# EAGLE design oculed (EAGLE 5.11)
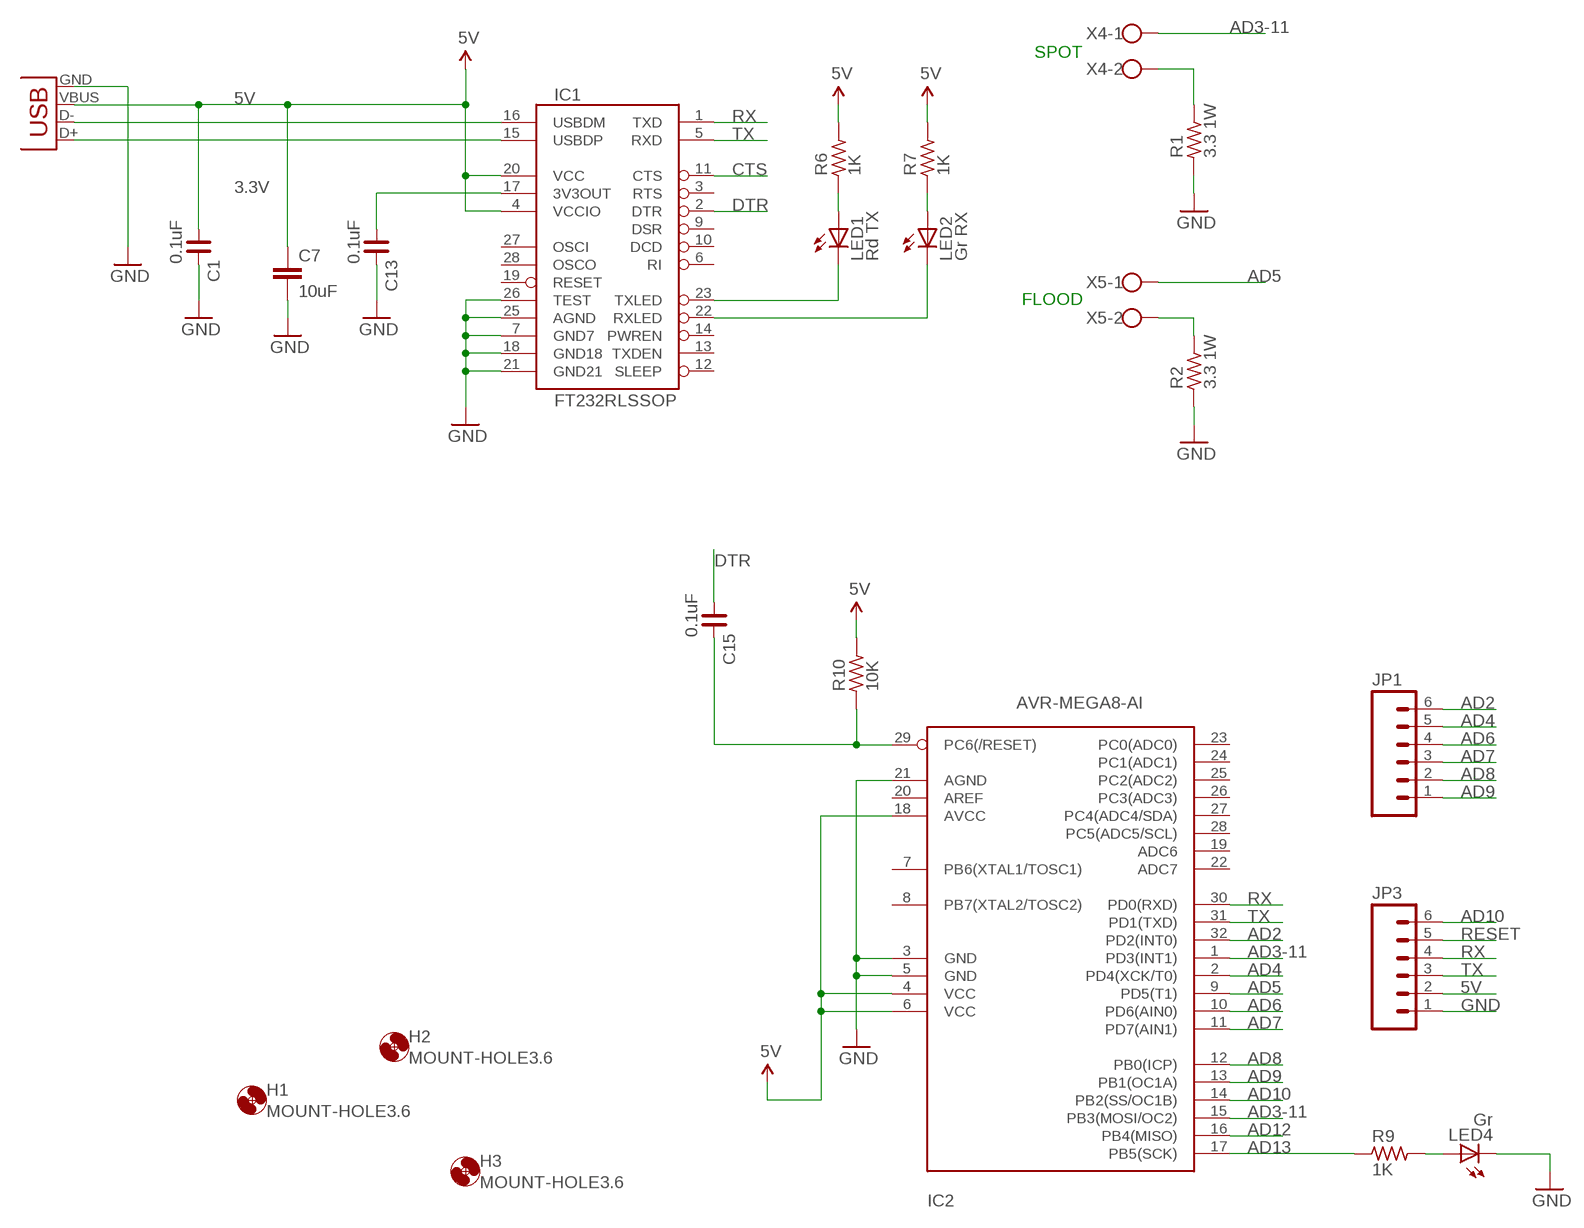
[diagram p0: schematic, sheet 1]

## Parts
C1  0.1uF  C_0805  [C0805]
C7  10uF  C-EUC3216  [C3216]
C13  0.1uF  C_0805  [C0805]
C15  0.1uF  C_0805  [C0805]
H1  MOUNT-HOLE3.6  [3,6]
H2  MOUNT-HOLE3.6  [3,6]
H3  MOUNT-HOLE3.6  [3,6]
IC1  FT232RLSSOP  [SSOP28DB]
IC2  AVR-MEGA8-AI  [TQFP32-08]
JP1  M06LONGPADS  [1X06_LONGPADS]
JP3  M06LONGPADS  [1X06_LONGPADS]
LED1  Rd TX  LEDCHIPLED_0805  [CHIPLED_0805]
LED2  Gr RX  LEDCHIPLED_0805  [CHIPLED_0805]
LED4  Gr  LEDCHIPLED_0805  [CHIPLED_0805]
R1  3.3 1W  R_2512  [R2512]
R2  3.3 1W  R_2512  [R2512]
R6  1K  R_0805  [R0805]
R7  1K  R_0805  [R0805]
R9  1K  R_0805  [R0805]
R10  10K  R_0805  [R0805]
X1  USBSMD  [USB-MINIB]
X4  W237-102  [W237-102]
X5  W237-102  [W237-102]

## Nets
3.3V: C13.1 IC1.17(3V3OUT)
5V [power]: C1.1 C7.1 IC1.4(VCCIO) IC1.20(VCC) IC2.4(VCC) IC2.6(VCC) IC2.18(AVCC) JP3.2 R6.2 R7.2 R10.2 X1.VBUS
AD2: IC2.32(PD2(INT0)) JP1.6
AD3-11: IC2.1(PD3(INT1)) IC2.15(PB3(MOSI/OC2)) X4.1
AD4: IC2.2(PD4(XCK/T0)) JP1.5
AD5: IC2.9(PD5(T1)) X5.1
AD6: IC2.10(PD6(AIN0)) JP1.4
AD7: IC2.11(PD7(AIN1)) JP1.3
AD8: IC2.12(PB0(ICP)) JP1.2
AD9: IC2.13(PB1(OC1A)) JP1.1
AD10: IC2.14(PB2(SS/OC1B)) JP3.6
AD12: IC2.16(PB4(MISO))
AD13: IC2.17(PB5(SCK)) R9.1
CTS: IC1.11(CTS)
DTR: C15.1 IC1.2(DTR)
GND [power]: C1.2 C7.2 C13.2 IC1.7(GND7) IC1.18(GND18) IC1.21(GND21) IC1.25(AGND) IC1.26(TEST) IC2.3(GND) IC2.5(GND) IC2.21(AGND) JP3.1 LED4.C R1.1 R2.1 X1.GND
N$1: IC1.16(USBDM) X1.D-
N$2: LED1.A R6.1
N$3: LED2.A R7.1
N$4: IC1.15(USBDP) X1.D+
N$5: IC1.23(TXLED) LED1.C
N$6: IC1.22(RXLED) LED2.C
N$7 [power]: R1.2 X4.2
N$8 [power]: R2.2 X5.2
N$10: LED4.A R9.2
RESET: C15.2 IC2.29(PC6(/RESET)) JP3.5 R10.1
RX: IC1.1(TXD) IC2.30(PD0(RXD)) JP3.4
TX: IC1.5(RXD) IC2.31(PD1(TXD)) JP3.3
Unconnected: IC1.3(RTS) IC1.6(RI) IC1.9(DSR) IC1.10(DCD) IC1.12(SLEEP) IC1.13(TXDEN) IC1.14(PWREN) IC1.19(RESET) IC1.27(OSCI) IC1.28(OSCO) IC2.7(PB6(XTAL1/TOSC1)) IC2.8(PB7(XTAL2/TOSC2)) IC2.19(ADC6) IC2.20(AREF) IC2.22(ADC7) IC2.23(PC0(ADC0)) IC2.24(PC1(ADC1)) IC2.25(PC2(ADC2)) IC2.26(PC3(ADC3)) IC2.27(PC4(ADC4/SDA)) IC2.28(PC5(ADC5/SCL))

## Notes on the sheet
- SPOT
- FLOOD

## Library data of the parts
C1 C13 C15 = rc-master-smd:C_: NON-POLARIZED CAP
C7 = rcl:C-EU: CAPACITOR, European symbol
H1-H3 = holes:MOUNT-HOLE: MOUNTING HOLE with drill center marker
IC1 = SparkFun:FT232RL: USB UART FT232RL 4th Generation USB UART (USB <-> Serial) Controller. Spark Fun Electronics SKU : COM-00650
IC2 = SparkFun:AVR-MEGA8: MICROCONTROLLER 8 Kbytes FLASH 1 kbytes SRAM 512 bytes EEPROM USART 6-channel 10 bit ADC 2-channel 8 bit ADC
JP1 JP3 = SparkFun:M06: Header 6 Standard 6-pin 0.1" header. Use with straight break away headers (SKU : PRT-00116), right angle break away headers (PRT-00553), swiss pins (PRT-00743), machine pins (PRT-00117), and female headers (PRT-00115). Molex polarized connector foot print use with SKU : PRT-08094 with associated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
LED1 LED2 LED4 = led:LED: LED
R1 R2 R6 R7 R9 R10 = rc-master-smd:R_: RESISTOR
X1 = SparkFun:USB: USB Connectors USB-B-PTH is fully proven SKU : PRT-00139 USB-miniB is fully proven SKU : PRT-00587 USB-A-PCB is untested. USB-A-H is throughly reviewed, but untested. Spark Fun Electronics SKU : PRT-00437 USB-B-SMT is throughly reviewed, but untested. Needs silkscreen touching up. USB-A-S has not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
X4 X5 = con-wago-500:W237-102: WAGO SCREW CLAMP

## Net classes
0 default: width 0.254 mm, drill 0.203 mm, clearance 0.203 mm
1 power: width 0.406 mm, drill 0.254 mm, clearance 0.305 mm

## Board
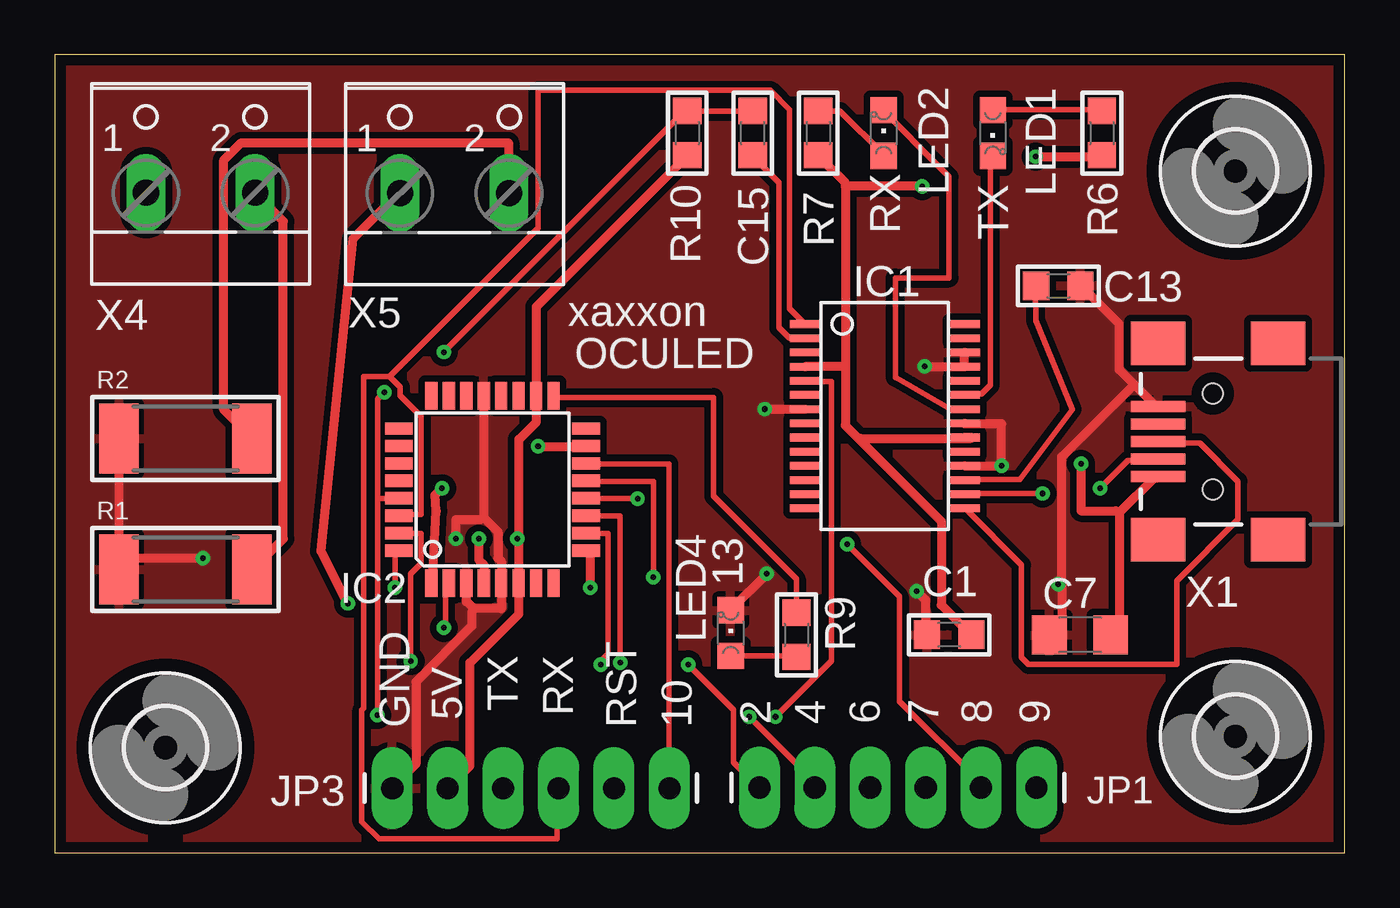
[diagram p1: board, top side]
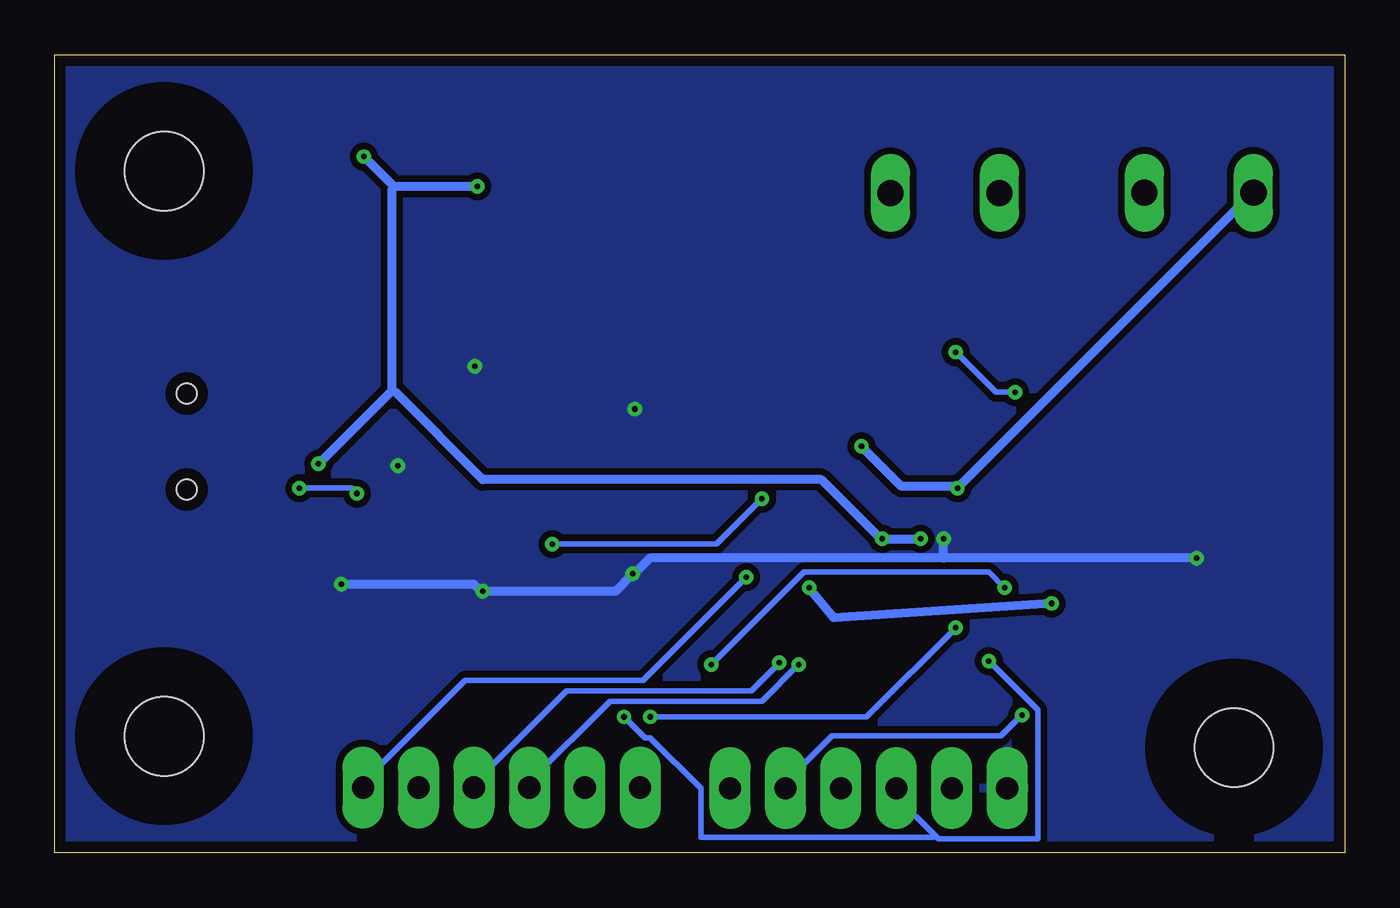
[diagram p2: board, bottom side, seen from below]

Size 59.14 x 36.6 mm. Coordinates in mm from the lower left corner, seen from the top.
Outline: 0,0 59.14,0 59.14,36.6 0,36.6 0,0
Copper layers (1*16): Top 0.035mm / dielectric 1.5mm / Bottom 0.035mm
Design rules "default *": minimum track width 8mil, minimum drill 10mil, track to track 8mil, track to pad 8mil, pad to pad 8mil, via to via 8mil, smd to smd 8mil, copper to edge 20mil, drill to drill 8mil, minimum pad ring 10mil, minimum via ring 8mil, stop-mask expansion 4mil, vias tented up to drill 0mil, thermal gap 10mil

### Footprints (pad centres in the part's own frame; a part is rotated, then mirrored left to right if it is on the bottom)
C0805 = smd 1.2 x 1.3: 1 -1.016,0; 2 1.016,0
C3216 = smd 1.6 x 1.8: 1 -1.4,0; 2 1.4,0
3,6 = hole 3.6: 0,0
SSOP28DB = smd 0.348 x 1.397: 1 -4.225,-3.656; 2 -3.575,-3.656; 3 -2.925,-3.656; 4 -2.275,-3.656; 5 -1.625,-3.656; 6 -0.975,-3.656; 7 -0.325,-3.656; 8 0.325,-3.656; 9 0.975,-3.656; 10 1.625,-3.656; 11 2.275,-3.656; 12 2.925,-3.656; 13 3.575,-3.656; 14 4.225,-3.656; 15 4.225,3.656; 16 3.575,3.656; 17 2.925,3.656; 18 2.275,3.656; 19 1.625,3.656; 20 0.975,3.656; 21 0.325,3.656; 22 -0.325,3.656; 23 -0.975,3.656; 24 -1.625,3.656; 25 -2.275,3.656; 26 -2.925,3.656; 27 -3.575,3.656; 28 -4.225,3.656
TQFP32-08 = smd 1.27 x 0.559: 1 -4.293,2.8; 2 -4.293,2; 3 -4.293,1.2; 4 -4.293,0.4; 5 -4.293,-0.4; 6 -4.293,-1.2; 7 -4.293,-2; 8 -4.293,-2.8; 17 4.293,-2.8; 18 4.293,-2; 19 4.293,-1.2; 20 4.293,-0.4; 21 4.293,0.4; 22 4.293,1.2; 23 4.293,2; 24 4.293,2.8 | smd 0.559 x 1.27: 9 -2.8,-4.293; 10 -2,-4.293; 11 -1.2,-4.293; 12 -0.4,-4.293; 13 0.4,-4.293; 14 1.2,-4.293; 15 2,-4.293; 16 2.8,-4.293; 25 2.8,4.293; 26 2,4.293; 27 1.2,4.293; 28 0.4,4.293; 29 -0.4,4.293; 30 -1.2,4.293; 31 -2,4.293; 32 -2.8,4.293
1X06_LONGPADS = drill 1.016 pad 1.88 long: 1 0,0; 2 2.54,0; 3 5.08,0; 4 7.62,0; 5 10.16,0; 6 12.7,0
CHIPLED_0805 = smd 1.2 x 1.2: A 0,-1.05; C 0,1.05
R2512 = smd 1.8 x 3.2: 1 -3.048,0; 2 3.048,0
R0805 = smd 1.2 x 1.3: 1 -1.016,0; 2 1.016,0
USB-MINIB = smd 2.5 x 0.5: D+ 2.5,0; D- 2.5,0.8; GND 2.5,-1.6; ID 2.5,-0.8; VBUS 2.5,1.6 | smd 2.5 x 2: GND@1 -3,-4.5; GND@2 -3,4.5; GND@3 2.5,4.5; GND@4 2.5,-4.5 | hole 0.9: 0,2.2; 0,-2.2
W237-102 = drill 1.194 long: 1 -2.5,-1.27; 2 2.5,-1.27

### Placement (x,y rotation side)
C1  41,10 180 top
C7  47,10 180 top
C13  46,26 0 top
C15  32,33 90 top
H1  54.12,31.26 0 top
H2  54.12,5.35 0 top
H3  5.08,4.83 0 top
IC1  38.05,20.02 270 top
IC2  20.07,16.66 90 top
JP1  45,3 180 top
JP3  15.48,2.97 0 top
LED1  43,33 180 top
LED2  38,33 0 top
LED4  30.99,10.08 0 top
R1  6,13 0 top
R2  6,19 0 top
R6  48,33 270 top
R7  35,33 270 top
R9  34,10 270 top
R10  29,33 270 top
X1  53.08,18.86 180 top
X4  6.69,31.53 0 top
X5  18.33,31.52 0 top

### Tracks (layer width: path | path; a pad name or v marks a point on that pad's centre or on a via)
3.3V
  Top 0.254: C13.1 44.96,26 44.97,24.4 46.64,20.33 44.25,17.12 41.76,17.12 IC1.17
5V  (via drill 0.25)
  Top 0.406: C7.1 48.8,10.4 48.8,15.6 | 48.8,15.6 50.4,17.2 50.56,17.2 X1.VBUS | 36.92,18.92 36.24,19.6 36.24,22.3 | 36.92,18.92 40.64,15.2 40.64,11.36 42,10 C1.1 | 36.24,30.56 36.24,30.72 35.04,31.92 R7.2 | 36.24,30.56 36.24,22.3 | v44.96,31.92 48,31.92 R6.2 | v39.76,30.56 36.24,30.56 | v47.04,17.84 47.04,15.68 48.64,15.68 48.8,15.6 | v19.44,14.4 19.44,13.44 19.68,13.2 19.68,12.4 IC2.4 | R10.2 28.96,31.92 22.08,25.04 22.08,21.12 IC2.18 22.08,20.88 22.08,19.76 21.28,18.96 21.28,14.56 v21.2,14.4 21.28,14.32 21.28,12.4 IC2.6 21.28,12.16 21.28,10.96 19.04,8.72 19.04,4 18.08,3.04 JP3.2 | 36.24,22.3 IC1.4 | IC1.20 42,19.05 42,19 36.92,19 36.92,18.92
  Bottom 0.406: 43.6,30.56 v44.96,31.92 | 43.6,30.56 v39.76,30.56 | 43.68,21.2 v47.04,17.84 | 43.68,21.2 43.68,30.4 43.6,30.56 | v19.44,14.4 v21.2,14.4 21.36,14.48 24,17.12 39.52,17.12 43.52,21.12 43.68,21.2
AD2  (via drill 0.25)
  Top 0.254: v15.6,12.16 15.6,13.68 15.76,13.84 IC2.32 | v29.04,8.64 31.12,6.56 31.12,4.16 32.24,3.04 JP1.6
  Bottom 0.254: v15.6,12.16 16.32,12.88 24.8,12.88 v29.04,8.64
AD3-11  (via drill 0.25)
  Top 0.254: IC2.1 17.33,12.51 | 24.32,18.64 IC2.15
  Top 0.406: 17.33,12.51 17.49,15.67 17.44,16.4 v17.76,16.72 | v22.16,18.64 24.32,18.64
  Bottom 0.254: 4.24,30.24 X4.1 | v17.76,16.72 17.84,16.8
  Bottom 0.406: v17.76,16.72 4.24,30.24 | v22.16,18.64 20.32,16.8 17.84,16.8
AD4  (via drill 0.25)
  Top 0.254: v17.84,10.32 17.92,10.4 17.92,12.24 18,12.32 IC2.2 | v31.84,6.24 34.8,3.28 34.8,3.04 JP1.5
  Bottom 0.254: v17.84,10.32 21.92,6.24 v31.84,6.24
AD5  (via drill 0.25)
  Top 0.254: 24.56,13.68 24.4,13.84 IC2.9 | 15.76,30.24 X5.1
  Top 0.406: v24.56,12.16 24.56,13.68 | v13.44,11.44 12.21,13.84 13.68,28.16 15.76,30.24
  Bottom 0.406: v24.56,12.16 23.42,10.78 v13.44,11.44
AD6  (via drill 0.25)
  Top 0.254: v25.04,8.64 25.04,8.8 25.36,9.12 25.36,14.64 24.4,14.64 IC2.10
  Bottom 0.254: v25.04,8.64 26.72,6.96 33.68,6.96 37.36,3.28 37.36,3.04 JP1.4
AD7  (via drill 0.25)
  Top 0.254: v25.92,8.72 25.92,15.44 24.4,15.44 IC2.11
  Bottom 0.254: v25.92,8.72 27.2,7.44 35.68,7.44 39.92,3.2 JP1.3
AD8  (via drill 0.25)
  Top 0.254: v26.72,16.24 24.4,16.24 IC2.12 | v36.32,14.16 38.72,11.76 38.72,6.96 42.4,3.28 42.4,3.04 JP1.2
  Bottom 0.254: v26.72,16.24 28.8,14.16 v36.32,14.16
AD9  (via drill 0.25)
  Top 0.254: v27.44,12.64 27.44,17.04 24.4,17.04 IC2.13
  Bottom 0.254: v27.44,12.64 32.16,7.92 40.32,7.92 44.96,3.28 44.96,3.04 JP1.1
AD10
  Top 0.254: IC2.14 24.4,17.84 28.16,17.84 28.16,3.04 JP3.6
AD13
  Top 0.254: IC2.17 22.88,20.88 30.2,20.88 30.2,16.36 34,12.56 R9.1
DTR
  Top 0.254: C15.1 32,31.92 33.2,30.72 33.2,24.08 33.68,23.6 34.32,23.6 IC1.2
GND  (via drill 0.25)
  Top 0.406: 19.2,11.2 18.88,11.52 18.88,12.32 IC2.3 | 19.2,11.2 20.48,11.2 20.48,12.32 IC2.5 20.48,12.56 20.48,13.36 20.32,13.52 20.32,14.72 19.68,15.36 | 19.68,15.36 19.68,20.88 IC2.21 | JP3.1 15.52,3.04 16.56,4.08 16.56,7.84 19.12,10.4 19.12,11.04 19.2,11.2 | R2.1 2.96,18.96 2.96,13.04 R1.1 3.12,13.52 v6.8,13.52 | v32.64,12.8 31.04,11.2 LED4.C | v39.52,12 39.92,11.6 39.92,10 C1.2 | 49.48,21.48 50.48,20.48 50.56,20.48 X1.GND | 49.48,21.48 48.8,22.16 48.8,24.24 47.04,26 C13.2 | C7.2 46.16,10.56 46.16,12.32 | 46.16,12.32 46.16,18.16 49.48,21.48 | v46,12.32 46.16,12.32 | v18.4,14.4 18.4,15.28 19.52,15.28 19.68,15.36 | IC1.7 v32.54,20.34 v32.54,20.35 | IC1.18 v43.4,17.75 43.4,19.67 41.71,19.67 IC1.21 | IC1.26 IC1.25 v39.88,22.3
  Bottom 0.406: v46,12.32 39.92,12.32 39.68,12.08 v39.52,12 33.44,12 v32.64,12.8 32.48,12.88 31.84,13.52 18.4,13.52 | v6.8,13.52 18.4,13.52 | 18.4,13.52 v18.4,14.4 | 32.54,20.3 v32.54,20.35 | v43.4,17.75 v43.41,17.75 43.41,17.82 | v39.88,22.3 v39.88,22.29 39.91,22.29 39.91,22.3
  pour Bottom: 0,0 59,0 59,37 0,37
  pour Top: 0,0 59,0 59,39 0,39
N$1  (via drill 0.25)
  Top 0.254: v45.28,16.48 41.76,16.48 IC1.16 | v47.92,16.72 49.2,18 50.56,18 X1.D-
  Bottom 0.254: v45.28,16.48 45.52,16.72 v47.92,16.72
N$2
  Top 0.254: LED1.A 43.04,34.08 48,34.08 R6.1
N$3
  Top 0.254: LED2.A 38,32 36,34 35.04,34 R7.1
N$4
  Top 0.254: IC1.15 41.76,15.76 44.32,13.2 44.32,8.96 44.64,8.64 51.44,8.64 51.44,12.48 54.24,15.28 54.24,17.04 52.48,18.8 50.64,18.8 X1.D+
N$5
  Top 0.254: LED1.C 42.96,31.92 42.88,31.84 42.88,21.44 42.48,21.04 41.76,21.04 IC1.23
N$6
  Top 0.254: LED2.C 38,34 40.56,31.44 41,31 41,26.36 38.53,26.36 38.53,21.8 38.56,21.8 40.96,20.4 41.68,20.4 IC1.22
N$7
  Top 0.406: R1.2 9.12,13.04 10.48,14.4 10.48,28.96 9.2,30.24 X4.2
N$8
  Top 0.406: R2.2 9.04,19.04 7.76,20.32 7.76,31.76 8.56,32.56 20.8,32.56 20.8,30.32 X5.2
N$10
  Top 0.254: LED4.A 31.04,9.04 34,9.04 R9.2
RESET  (via drill 0.25)
  Top 0.254: C15.2 32,34 29.04,34 R10.1 28.88,34 v17.84,22.96 | 14.8,16.24 15.76,16.24 IC2.29 | v14.8,6.32 14.8,16.24 | v15.12,21.12 14.8,20.8 14.8,16.24
  Bottom 0.254: v14.8,6.32 15.76,5.36 23.52,5.36 25.6,3.28 25.6,3.04 JP3.5 | v17.84,22.96 16,21.12 v15.12,21.12
RX
  Top 0.254: 15.36,21.84 15.84,21.36 15.84,20.96 16.8,20 16.8,15.52 15.84,15.52 IC2.30 | 15.36,21.84 14.16,21.84 14.16,6.64 14.08,6.56 14.08,1.44 14.88,0.64 23.04,0.64 23.04,2.96 JP3.4 | IC1.1 34.32,24.32 33.68,24.96 33.68,34.08 32.8,34.96 22.16,34.96 22.16,28.64 15.36,21.84
TX  (via drill 0.25)
  Top 0.254: v16.32,8.8 16.32,12.8 16.8,13.28 16.8,14.64 15.84,14.64 IC2.31 | v33.04,6.24 35.6,8.8 35.6,21.6 34.4,21.6 IC1.5
  Bottom 0.254: v16.32,8.8 14.08,6.56 14.08,0.64 18.64,0.64 18.8,0.8 | 18.8,0.8 20.56,2.56 JP3.3 | v33.04,6.24 32.08,5.28 31.84,5.28 29.52,2.96 29.52,0.72 18.88,0.72 18.8,0.8

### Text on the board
tNames: RX | TX | xaxxon | OCULED | 13 | IC2 | GND | TX | RX | 5V | RST | 10 | 2 | 4 | 6 | 7 | 8 | 9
